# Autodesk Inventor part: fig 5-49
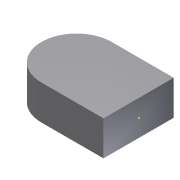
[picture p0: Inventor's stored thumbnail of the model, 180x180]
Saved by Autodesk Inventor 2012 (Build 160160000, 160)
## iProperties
Created: 2010-02
Part Number: fig 5-49
Document SubType Name: Modeling
Designer: CADSoft
Density: 1 g/cm^3
Material: Default
Author: CADSoft
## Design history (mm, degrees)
sketch "Sketch1"
  geometry: L1 (-17.92, 20.292)-(0, 20.292); L2 (0, 20.292)-(0, 0); L3 (0, 0)-(-17.92, 0); A1 r 10.146 centre (-17.92, 10.146) between (-17.92, 20.292) and (-17.92, 0)
  constraints: 6 end point, 2 horizontal, 2 point on circle, 2 tangent, 1 centre point, 1 vertical
extrude "Extrusion1" new body sketch "Sketch1" distance "d0" = 10; taper "d1" = 0 deg
workpoint "Work Point1"
body "Solid1"
